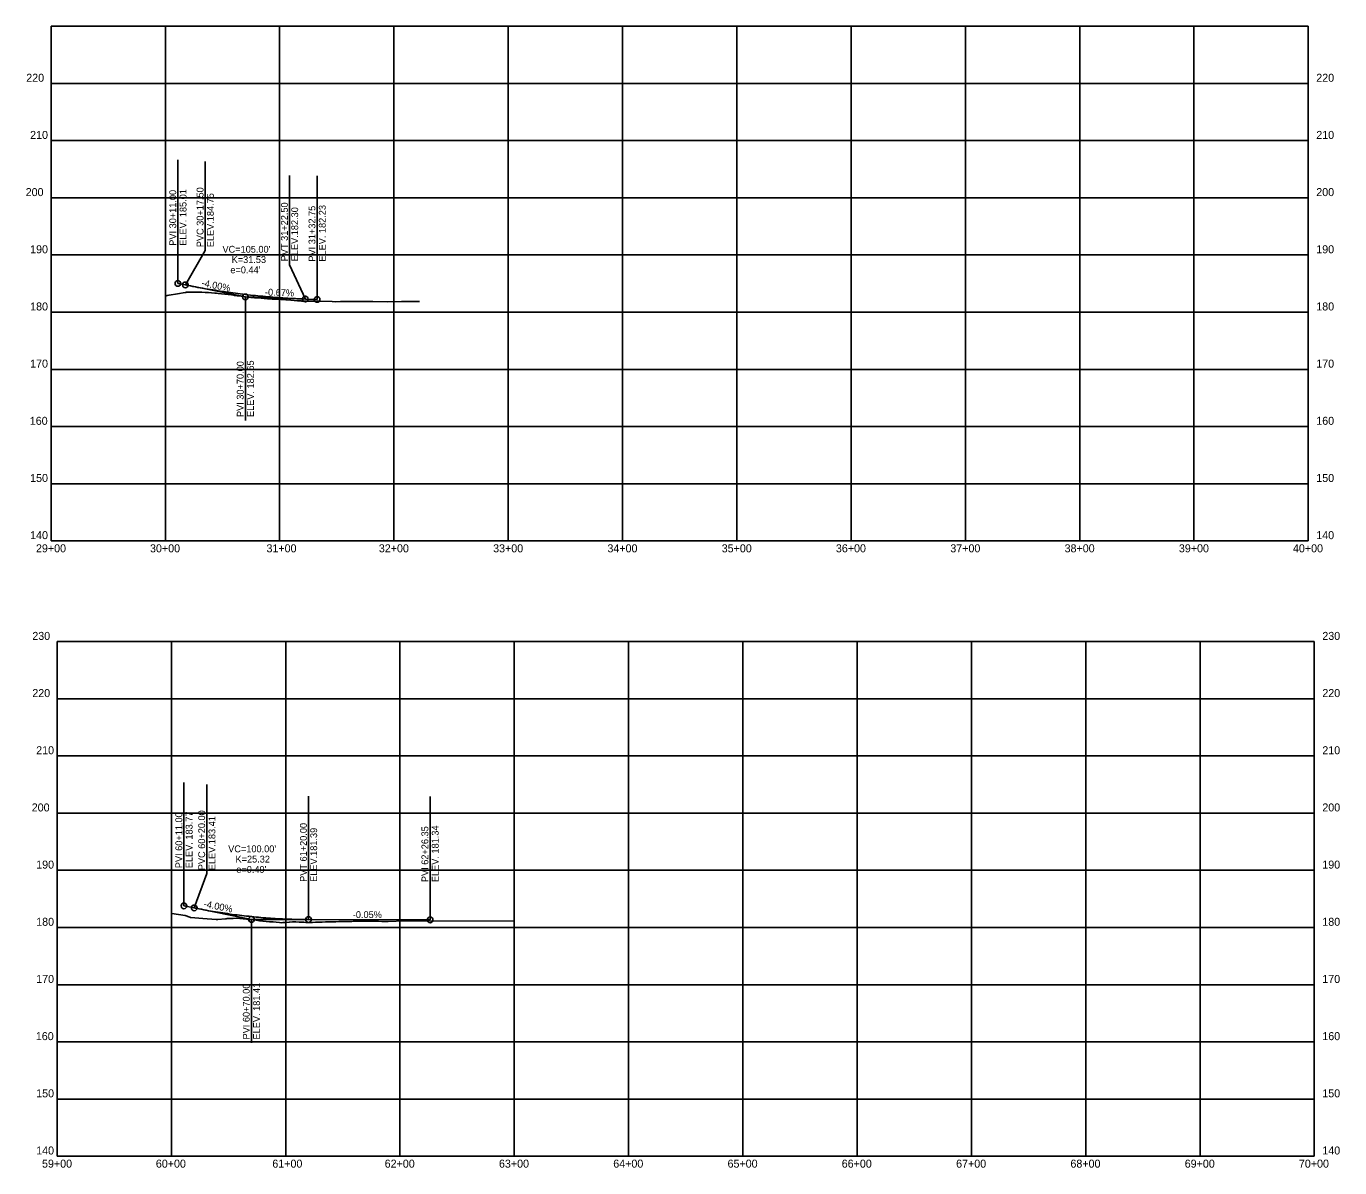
# Model space of a CAD drawing. Extents: x 1 to 1477871, y 1 to 1872901.
# Drawn here: x 1444745 to 1445894, y 1852226 to 1853224 of the extents above; entities that cross this region are included whole.
import ezdxf

# ---------------------------------------------------------------- set-up
doc = ezdxf.new("R2010")
doc.units = 0
for name, color, linetype in [('R_Axis', 7, 'Continuous'), ('R_Axis Annot', 7, 'Continuous'), ('R_Exist Surface', 7, 'Continuous'), ('R_Grid', 7, 'Continuous'), ('R_Vert Alg', 7, 'Continuous'), ('R_Vert Alg Annot', 7, 'Continuous')]:
    doc.layers.add(name, color=color, linetype=linetype)

msp = doc.modelspace()

# ---------------------------------------------------------------- linework, layer by layer
at = {"layer": 'R_Axis'}
for p, q in [((1444766.3, 1852773.7), (1444766.3, 1853223.7)), ((1445866.3, 1852773.7), (1445866.3, 1853223.7)), ((1444766.3, 1852773.7), (1445866.3, 1852773.7)), ((1444771.6, 1852235.6), (1444771.6, 1852685.6)), ((1445871.6, 1852235.6), (1445871.6, 1852685.6)), ((1444771.6, 1852235.6), (1445871.6, 1852235.6))]:
    msp.add_line(p, q, dxfattribs=at)
at = {"layer": 'R_Exist Surface'}
for points in [[(1444866.3, 1852987.7), (1444868, 1852988.3), (1444869.6, 1852988.7), (1444876.8, 1852989.7), (1444883.7, 1852990.9), (1444884.1, 1852991), (1444884.9, 1852991.2), (1444886.6, 1852991.3), (1444888, 1852991.3), (1444889.4, 1852991.3), (1444892.3, 1852991.3), (1444895.2, 1852991.2), (1444895.6, 1852991.2), (1444898.1, 1852991.1), (1444901, 1852991), (1444903.9, 1852990.9), (1444904.2, 1852990.9), (1444906.7, 1852990.7), (1444909.6, 1852990.4), (1444911, 1852990.3), (1444912.5, 1852990.1), (1444915.4, 1852989.8), (1444915.5, 1852989.8), (1444918.3, 1852989.5), (1444921.2, 1852989.1), (1444924.1, 1852988.8), (1444926.2, 1852988.5), (1444926.9, 1852988.4), (1444929, 1852988.1), (1444929.8, 1852988), (1444932.7, 1852987.6), (1444935.6, 1852987.2), (1444938.5, 1852986.8), (1444941.1, 1852986.5), (1444941.4, 1852986.5), (1444944.2, 1852986.3), (1444944.8, 1852986.3), (1444947.1, 1852986.1), (1444950, 1852985.9), (1444952.9, 1852985.6), (1444955.8, 1852985.4), (1444956.2, 1852985.4), (1444958.7, 1852985.3), (1444959.8, 1852985.2), (1444961.6, 1852985.1), (1444964.4, 1852985), (1444967.3, 1852984.9), (1444970.2, 1852984.8), (1444970.6, 1852984.8), (1444971.8, 1852984.5), (1444973.1, 1852984.4), (1444976, 1852984.2), (1444978.9, 1852984), (1444981.8, 1852983.7), (1444984.6, 1852983.5), (1444985.2, 1852983.5), (1444985.7, 1852983.4), (1444986.5, 1852983.4), (1444987.5, 1852983.4), (1444990.4, 1852983.4), (1444991.3, 1852983.3), (1444993.3, 1852983.3), (1444996.2, 1852983.3), (1444999.1, 1852983.2), (1445000.7, 1852983.2), (1445012.2, 1852982.9), (1445015.6, 1852982.8), (1445019.5, 1852982.9), (1445030.6, 1852982.9), (1445043.1, 1852983), (1445045.6, 1852983), (1445047.9, 1852983), (1445060.6, 1852982.8), (1445073, 1852983), (1445075.3, 1852983), (1445075.6, 1852983), (1445075.9, 1852983), (1445088.8, 1852982.9)], [(1444871.6, 1852447.7), (1444871.9, 1852447.7), (1444883.7, 1852446), (1444887.6, 1852444.5), (1444887.9, 1852444.4), (1444888.5, 1852444.4), (1444899.2, 1852443.5), (1444910.9, 1852442.7), (1444911.8, 1852442.6), (1444912.3, 1852442.6), (1444918.9, 1852443.3), (1444919.5, 1852443.3), (1444920.4, 1852443.4), (1444925.7, 1852443.6), (1444928.5, 1852443.7), (1444929.2, 1852443.7), (1444931.4, 1852443.6), (1444934.3, 1852443.3), (1444935.7, 1852443.2), (1444937.2, 1852443), (1444939.1, 1852442.8), (1444940.1, 1852442.7), (1444943, 1852442.4), (1444944, 1852442.3), (1444945.9, 1852442), (1444948.8, 1852441.5), (1444951.6, 1852441), (1444952, 1852441), (1444954.5, 1852440.8), (1444957.4, 1852440.7), (1444960.3, 1852440.5), (1444960.5, 1852440.5), (1444963.2, 1852440.2), (1444966.1, 1852440), (1444967.7, 1852439.8), (1444969, 1852439.9), (1444971.9, 1852440.1), (1444974.7, 1852440.4), (1444974.9, 1852440.4), (1444977.6, 1852440.5), (1444978.9, 1852440.6), (1444980.5, 1852440.5), (1444983.4, 1852440.4), (1444984.4, 1852440.4), (1444986.3, 1852440.3), (1444987.4, 1852440.3), (1444989.2, 1852440.1), (1444990.1, 1852440), (1444992.1, 1852440.1), (1444995, 1852440.1), (1444997.8, 1852440.2), (1445000.3, 1852440.3), (1445000.7, 1852440.3), (1445003.6, 1852440.4), (1445006.5, 1852440.5), (1445008.3, 1852440.6), (1445009.4, 1852440.6), (1445012.3, 1852440.6), (1445015.2, 1852440.7), (1445015.5, 1852440.7), (1445018.1, 1852440.8), (1445021, 1852440.8), (1445023.8, 1852440.8), (1445026.7, 1852440.9), (1445029.3, 1852440.9), (1445029.6, 1852440.9), (1445030.6, 1852441), (1445032.5, 1852441), (1445035.4, 1852441), (1445038.3, 1852441.1), (1445038.6, 1852441.1), (1445041.2, 1852441.1), (1445044.1, 1852441.1), (1445045.6, 1852441.1), (1445046, 1852441.1), (1445046.9, 1852441.1), (1445049.8, 1852441), (1445052.7, 1852441), (1445055.6, 1852440.9), (1445060.6, 1852440.8), (1445061.3, 1852440.8), (1445075.6, 1852441.3), (1445076.3, 1852441.3), (1445090.6, 1852441.3), (1445091.3, 1852441.3), (1445171.6, 1852441.2)]]:
    msp.add_lwpolyline(points, dxfattribs=at)
at = {"layer": 'R_Grid'}
for p, q in [((1444766.3, 1853223.7), (1445866.3, 1853223.7)), ((1444766.3, 1853223.7), (1445866.3, 1853223.7)), ((1444866.3, 1852773.7), (1444866.3, 1853223.7)), ((1444966.3, 1852773.7), (1444966.3, 1853223.7)), ((1445066.3, 1852773.7), (1445066.3, 1853223.7)), ((1445166.3, 1852773.7), (1445166.3, 1853223.7)), ((1445266.3, 1852773.7), (1445266.3, 1853223.7)), ((1445366.3, 1852773.7), (1445366.3, 1853223.7)), ((1445466.3, 1852773.7), (1445466.3, 1853223.7)), ((1445566.3, 1852773.7), (1445566.3, 1853223.7)), ((1445666.3, 1852773.7), (1445666.3, 1853223.7)), ((1445766.3, 1852773.7), (1445766.3, 1853223.7)), ((1444766.3, 1853173.7), (1445866.3, 1853173.7)), ((1444766.3, 1853123.7), (1445866.3, 1853123.7)), ((1444766.3, 1853073.7), (1445866.3, 1853073.7)), ((1444766.3, 1853023.7), (1445866.3, 1853023.7)), ((1444766.3, 1852973.7), (1445866.3, 1852973.7)), ((1444766.3, 1852923.7), (1445866.3, 1852923.7)), ((1444766.3, 1852873.7), (1445866.3, 1852873.7)), ((1444766.3, 1852823.7), (1445866.3, 1852823.7)), ((1444771.6, 1852685.6), (1445871.6, 1852685.6)), ((1444771.6, 1852685.6), (1445871.6, 1852685.6)), ((1444871.6, 1852235.6), (1444871.6, 1852685.6)), ((1444971.6, 1852235.6), (1444971.6, 1852685.6)), ((1445071.6, 1852235.6), (1445071.6, 1852685.6)), ((1445171.6, 1852235.6), (1445171.6, 1852685.6)), ((1445271.6, 1852235.6), (1445271.6, 1852685.6)), ((1445371.6, 1852235.6), (1445371.6, 1852685.6)), ((1445471.6, 1852235.6), (1445471.6, 1852685.6)), ((1445571.6, 1852235.6), (1445571.6, 1852685.6)), ((1445671.6, 1852235.6), (1445671.6, 1852685.6)), ((1445771.6, 1852235.6), (1445771.6, 1852685.6)), ((1444771.6, 1852635.6), (1445871.6, 1852635.6)), ((1444771.6, 1852585.6), (1445871.6, 1852585.6)), ((1444771.6, 1852535.6), (1445871.6, 1852535.6)), ((1444771.6, 1852485.6), (1445871.6, 1852485.6)), ((1444771.6, 1852435.6), (1445871.6, 1852435.6)), ((1444771.6, 1852385.6), (1445871.6, 1852385.6)), ((1444771.6, 1852335.6), (1445871.6, 1852335.6)), ((1444771.6, 1852285.6), (1445871.6, 1852285.6))]:
    msp.add_line(p, q, dxfattribs=at)
at = {"layer": 'R_Vert Alg'}
for p, q in [((1444877.3, 1852998.8), (1444883.8, 1852997.5)), ((1444883.8, 1852997.5), (1444936.3, 1852987)), ((1444936.3, 1852987), (1444988.8, 1852985.2)), ((1444988.8, 1852985.2), (1444999.1, 1852984.9)), ((1444882.6, 1852454.5), (1444891.6, 1852452.7)), ((1444891.6, 1852452.7), (1444941.6, 1852442.7)), ((1444941.6, 1852442.7), (1444991.6, 1852442.5)), ((1444991.6, 1852442.5), (1445097.9, 1852442.3))]:
    msp.add_line(p, q, dxfattribs=at)
for points in [[(1444883.8, 1852997.5), (1444886, 1852997), (1444888.2, 1852996.6), (1444890.4, 1852996.2), (1444892.6, 1852995.8), (1444894.7, 1852995.4), (1444896.9, 1852995), (1444899.1, 1852994.6), (1444901.3, 1852994.2), (1444903.5, 1852993.9), (1444905.7, 1852993.5), (1444907.9, 1852993.1), (1444910.1, 1852992.8), (1444912.2, 1852992.4), (1444914.4, 1852992.1), (1444916.6, 1852991.8), (1444918.8, 1852991.5), (1444921, 1852991.1), (1444923.2, 1852990.8), (1444925.4, 1852990.5), (1444927.6, 1852990.2), (1444929.7, 1852990), (1444931.9, 1852989.7), (1444934.1, 1852989.4), (1444938.5, 1852988.9), (1444940.7, 1852988.7), (1444942.9, 1852988.4), (1444945.1, 1852988.2), (1444947.2, 1852988), (1444949.4, 1852987.8), (1444951.6, 1852987.6), (1444953.8, 1852987.4), (1444956, 1852987.2), (1444958.2, 1852987), (1444960.4, 1852986.8), (1444962.6, 1852986.6), (1444964.7, 1852986.5), (1444966.9, 1852986.3), (1444969.1, 1852986.2), (1444971.3, 1852986), (1444973.5, 1852985.9), (1444975.7, 1852985.8), (1444977.9, 1852985.7), (1444980.1, 1852985.6), (1444982.2, 1852985.5), (1444984.4, 1852985.4), (1444986.6, 1852985.3), (1444988.8, 1852985.2)], [(1444891.6, 1852452.7), (1444893.7, 1852452.3), (1444895.7, 1852451.9), (1444897.8, 1852451.5), (1444899.9, 1852451.1), (1444902, 1852450.7), (1444904.1, 1852450.3), (1444906.2, 1852450), (1444908.2, 1852449.6), (1444910.3, 1852449.3), (1444912.4, 1852448.9), (1444914.5, 1852448.6), (1444916.6, 1852448.3), (1444918.7, 1852448), (1444920.7, 1852447.7), (1444922.8, 1852447.4), (1444924.9, 1852447.1), (1444927, 1852446.8), (1444929.1, 1852446.6), (1444931.2, 1852446.3), (1444933.2, 1852446), (1444935.3, 1852445.8), (1444937.4, 1852445.6), (1444939.5, 1852445.4), (1444943.7, 1852444.9), (1444945.7, 1852444.7), (1444947.8, 1852444.5), (1444949.9, 1852444.4), (1444952, 1852444.2), (1444954.1, 1852444), (1444956.2, 1852443.9), (1444958.2, 1852443.7), (1444960.3, 1852443.6), (1444962.4, 1852443.5), (1444964.5, 1852443.3), (1444966.6, 1852443.2), (1444968.7, 1852443.1), (1444970.7, 1852443), (1444972.8, 1852442.9), (1444974.9, 1852442.9), (1444977, 1852442.8), (1444979.1, 1852442.7), (1444981.2, 1852442.7), (1444983.2, 1852442.6), (1444985.3, 1852442.6), (1444987.4, 1852442.6), (1444989.5, 1852442.5), (1444991.6, 1852442.5)]]:
    msp.add_lwpolyline(points, dxfattribs=at)
at = {"layer": 'R_Vert Alg Annot'}
for p, q in [((1444877.3, 1853028.8), (1444877.3, 1853106.8)), ((1444901.2, 1853027.5), (1444901.2, 1853105.5)), ((1444975, 1853015.2), (1444975, 1853093.2)), ((1444999.1, 1853014.9), (1444999.1, 1853092.9)), ((1444877.3, 1852998.8), (1444877.3, 1853028.8)), ((1444883.8, 1852997.5), (1444901.2, 1853027.5)), ((1444988.8, 1852985.2), (1444975, 1853015.2)), ((1444999.1, 1852984.9), (1444999.1, 1853014.9)), ((1444936.3, 1852987), (1444936.3, 1852957)), ((1444936.3, 1852957), (1444936.3, 1852879)), ((1444882.6, 1852484.5), (1444882.6, 1852562.5)), ((1444902.6, 1852482.7), (1444902.6, 1852560.7)), ((1444991.6, 1852472.5), (1444991.6, 1852550.5)), ((1445097.9, 1852472.3), (1445097.9, 1852550.3)), ((1444882.6, 1852454.5), (1444882.6, 1852484.5)), ((1444891.6, 1852452.7), (1444902.6, 1852482.7)), ((1444991.6, 1852442.5), (1444991.6, 1852472.5)), ((1445097.9, 1852442.3), (1445097.9, 1852472.3)), ((1444941.6, 1852442.7), (1444941.6, 1852412.7)), ((1444941.6, 1852412.7), (1444941.6, 1852334.7))]:
    msp.add_line(p, q, dxfattribs=at)
for centre in [(1444877.3, 1852998.8), (1444883.8, 1852997.5), (1444936.3, 1852987), (1444988.8, 1852985.2), (1444999.1, 1852984.9), (1444882.6, 1852454.5), (1444891.6, 1852452.7), (1444941.6, 1852442.7), (1444991.6, 1852442.5), (1445097.9, 1852442.3)]:
    msp.add_circle(centre, 2.5, dxfattribs=at)

# ---------------------------------------------------------------- texts
at = {"layer": 'R_Axis Annot'}
for s, height, p in [('220', 7, (1444744.6, 1853175.2)), ('220', 7, (1445873.3, 1853175.2)), ('210', 7, (1444748, 1853125.2)), ('210', 7, (1445873.3, 1853125.2)), ('200', 7, (1444744.1, 1853075.2)), ('200', 7, (1445873.3, 1853075.2)), ('190', 7, (1444748, 1853025.2)), ('190', 7, (1445873.3, 1853025.2)), ('180', 7, (1444748, 1852975.2)), ('180', 7, (1445873.3, 1852975.2)), ('170', 7, (1444748, 1852925.2)), ('170', 7, (1445873.3, 1852925.2)), ('160', 7, (1444747.7, 1852875.2)), ('160', 7, (1445873.3, 1852875.2)), ('150', 7, (1444748, 1852825.2)), ('150', 7, (1445873.3, 1852825.2)), ('140', 7, (1444748, 1852775.2)), ('140', 7, (1445873.3, 1852775.2)), ('29+00', 7, (1444753.1, 1852763.7)), ('-', 0.0001, (1444766.3, 1852773.7)), ('30+00', 7, (1444852.9, 1852763.7)), ('31+00', 7, (1444954.8, 1852763.7)), ('32+00', 7, (1445053.1, 1852763.7)), ('33+00', 7, (1445153.1, 1852763.7)), ('34+00', 7, (1445253.1, 1852763.7)), ('35+00', 7, (1445353.1, 1852763.7)), ('36+00', 7, (1445453, 1852763.7)), ('37+00', 7, (1445553.1, 1852763.7)), ('38+00', 7, (1445653.1, 1852763.7)), ('39+00', 7, (1445753.1, 1852763.7)), ('40+00', 7, (1445852.9, 1852763.7)), ('230', 7, (1444749.9, 1852687.1)), ('230', 7, (1444749.9, 1852687.1)), ('230', 7, (1445878.6, 1852687.1)), ('230', 7, (1445878.6, 1852687.1)), ('220', 7, (1444749.9, 1852637.1)), ('220', 7, (1445878.6, 1852637.1)), ('210', 7, (1444753.3, 1852587.1)), ('210', 7, (1445878.6, 1852587.1)), ('200', 7, (1444749.4, 1852537.1)), ('200', 7, (1445878.6, 1852537.1)), ('190', 7, (1444753.3, 1852487.1)), ('190', 7, (1445878.6, 1852487.1)), ('180', 7, (1444753.3, 1852437.1)), ('180', 7, (1445878.6, 1852437.1)), ('170', 7, (1444753.3, 1852387.1)), ('170', 7, (1445878.6, 1852387.1)), ('160', 7, (1444753, 1852337.1)), ('160', 7, (1445878.6, 1852337.1)), ('150', 7, (1444753.3, 1852287.1)), ('150', 7, (1445878.6, 1852287.1)), ('140', 7, (1444753.3, 1852237.1)), ('140', 7, (1445878.6, 1852237.1)), ('59+00', 7, (1444758.4, 1852225.6)), ('-', 0.0001, (1444771.6, 1852235.6)), ('60+00', 7, (1444858, 1852225.6)), ('61+00', 7, (1444959.9, 1852225.6)), ('62+00', 7, (1445058.2, 1852225.6)), ('63+00', 7, (1445158.2, 1852225.6)), ('64+00', 7, (1445258.2, 1852225.6)), ('65+00', 7, (1445358.2, 1852225.6)), ('66+00', 7, (1445458.1, 1852225.6)), ('67+00', 7, (1445558.2, 1852225.6)), ('68+00', 7, (1445658.2, 1852225.6)), ('69+00', 7, (1445758.2, 1852225.6)), ('70+00', 7, (1445858.1, 1852225.6))]:
    msp.add_text(s, height=height, dxfattribs=at).set_placement(p)
at = {"layer": 'R_Vert Alg Annot'}
for s, rotation, p in [('PVI 30+11.00', 90, (1444875.8, 1853031.8)), ('ELEV. 185.01', 90, (1444884.8, 1853031.8)), ('PVC 30+17.50', 90, (1444899.7, 1853030.5)), ('ELEV.184.75', 90, (1444908.7, 1853030.5)), ('PVT 31+22.50', 90, (1444973.5, 1853018.2)), ('ELEV.182.30', 90, (1444982.5, 1853018.2)), ('PVI 31+32.75', 90, (1444997.6, 1853017.9)), ('ELEV. 182.23', 90, (1445006.6, 1853017.9)), ('-4.00%', 348.6901, (1444897.6, 1852996.6)), ('-0.67%', 358.0695, (1444953.4, 1852988.3)), ('PVI 30+70.00', 90, (1444934.8, 1852882)), ('ELEV. 182.65', 90, (1444943.8, 1852882)), ('ELEV. 183.77', 90, (1444890.1, 1852487.5)), ('PVC 60+20.00', 90, (1444901.1, 1852485.7)), ('PVI 60+11.00', 90, (1444881.1, 1852487.5)), ('ELEV.183.41', 90, (1444910.1, 1852485.7)), ('PVT 61+20.00', 90, (1444990.1, 1852475.5)), ('ELEV.181.39', 90, (1444999.1, 1852475.5)), ('PVI 62+26.35', 90, (1445096.4, 1852475.3)), ('ELEV. 181.34', 90, (1445105.4, 1852475.3)), ('-4.00%', 348.6901, (1444899.5, 1852453.6)), ('-0.05%', 359.8514, (1445030.3, 1852443.9)), ('PVI 60+70.00', 90, (1444940.1, 1852337.7)), ('ELEV. 181.41', 90, (1444949.1, 1852337.7))]:
    msp.add_text(s, height=6, rotation=rotation, dxfattribs=at).set_placement(p)
for s, p in [("VC=105.00'", (1444916.3, 1853025.7)), ('K=31.53', (1444924.3, 1853016.7)), ("e=0.44'", (1444923.2, 1853007.7)), ("VC=100.00'", (1444921.3, 1852501.4)), ('K=25.32', (1444927.7, 1852492.4)), ("e=0.49'", (1444928.4, 1852483.4))]:
    msp.add_text(s, height=6, dxfattribs=at).set_placement(p)

doc.saveas('drawing.dxf')
